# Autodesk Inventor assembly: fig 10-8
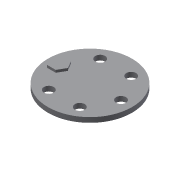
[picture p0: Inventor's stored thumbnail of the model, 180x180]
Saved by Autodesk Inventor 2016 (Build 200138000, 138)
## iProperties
Created: 2008-05
Part Number: fig 10-8
Document SubType Name: Assembly
Designer: CADCIM
Author: CADCIM
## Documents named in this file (3)
- D:\KAVITA\Autodesk Inventor_ 2016 Project_Kavita\Inventor_Part Files\Inventor_2016_Part\c10_Inv_2016\c10_inv_2016_prt\fig 10-8.iam
- D:\KAVITA\Autodesk Inventor_ 2016 Project_Kavita\Inventor_Part Files\Inventor_2016_Part\c10_Inv_2016\c10_inv_2016_prt\Part4.ipt
- D:\KAVITA\Autodesk Inventor_ 2016 Project_Kavita\Inventor_Part Files\Inventor_2016_Part\c10_Inv_2016\c10_inv_2016_prt\Part5.ipt
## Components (2 placed, 2 different names)
1. Part4:1
2. Part5:1
